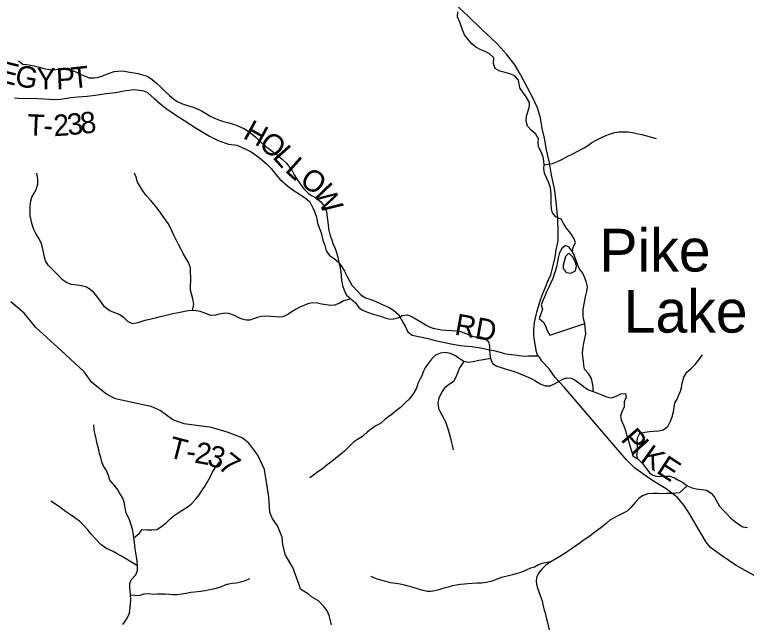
# Model space of a CAD drawing. Extents: x 1578669 to 1989827, y 208020 to 553079.
# Drawn here: x 1756635 to 1766909, y 418953 to 427488 of the extents above; entities that cross this region are included whole.
import ezdxf

# ---------------------------------------------------------------- set-up
doc = ezdxf.new("R2010")
doc.units = 0
for name, color, linetype in [('GM_X_County_Road', 7, 'Continuous'), ('GM_X_County_Road_Text', 7, 'Continuous'), ('GM_X_Major_River', 7, 'Continuous'), ('GM_X_Minor_Lake', 7, 'Continuous'), ('GM_X_Minor_Lake_Text', 7, 'Continuous'), ('GM_X_Minor_River', 7, 'Continuous'), ('GM_X_Township_Road', 7, 'Continuous'), ('GM_X_Township_Road_Text', 7, 'Continuous')]:
    doc.layers.add(name, color=color, linetype=linetype)

msp = doc.modelspace()

# ---------------------------------------------------------------- linework, layer by layer
at = {"layer": 'GM_X_County_Road'}
msp.add_lwpolyline([(1767103, 419565), (1766766, 419751), (1766561, 419891), (1766407, 420005), (1766344, 420080), (1766269, 420203), (1766105, 420488), (1766032, 420597), (1765943, 420706), (1765785, 420826), (1765620, 420928), (1765503, 421004), (1765337, 421122), (1765228, 421233), (1765049, 421440), (1764349, 422257), (1764226, 422391), (1764138, 422512), (1764039, 422622), (1764002, 422675), (1763986, 422694), (1763970, 422721), (1763957, 422767), (1763951, 422809), (1763934, 422909), (1763927, 422984), (1763926, 423058), (1763935, 423164), (1763965, 423308), (1763998, 423420), (1764021, 423498), (1764049, 423572), (1764088, 423659), (1764123, 423743), (1764162, 423835), (1764195, 423963), (1764223, 424083), (1764240, 424185), (1764265, 424311), (1764268, 424449), (1764260, 424620), (1764242, 424810), (1764219, 425017), (1764171, 425238), (1764145, 425407), (1764103, 425587), (1764075, 425752), (1764044, 425887), (1764020, 426037), (1763974, 426178), (1763899, 426337), (1763829, 426468), (1763739, 426648), (1763659, 426783), (1763540, 426931), (1763416, 427074), (1763321, 427164), (1763193, 427279), (1762999, 427472), (1762817, 427640)], dxfattribs=at)
at = {"layer": 'GM_X_Major_River'}
msp.add_lwpolyline([(1764466, 424156), (1764479, 424220), (1764508, 424282), (1764489, 424341), (1764442, 424412), (1764384, 424491), (1764351, 424542), (1764308, 424613), (1764234, 424646), (1764187, 424703), (1764173, 424759), (1764170, 424826), (1764169, 424886), (1764170, 424950), (1764165, 425022), (1764152, 425075), (1764135, 425127), (1764102, 425194), (1764076, 425261), (1764067, 425325), (1764070, 425379), (1764067, 425431), (1764054, 425492), (1764027, 425560), (1763988, 425633), (1763984, 425695), (1763988, 425745), (1763954, 425810), (1763893, 425859), (1763836, 425919), (1763815, 425993), (1763820, 426061), (1763844, 426135), (1763865, 426203), (1763866, 426255), (1763819, 426334), (1763778, 426387), (1763729, 426458), (1763719, 426518), (1763711, 426569), (1763660, 426626), (1763587, 426657), (1763523, 426674), (1763448, 426696), (1763380, 426731), (1763358, 426800), (1763365, 426880), (1763304, 426935), (1763249, 426964), (1763181, 426991), (1763108, 427029), (1763055, 427076), (1763002, 427139), (1762949, 427206), (1762922, 427275), (1762884, 427380), (1762851, 427455), (1762859, 427525)], dxfattribs=at)
at = {"layer": 'GM_X_Minor_Lake'}
for points in [[(1764466, 424156), (1764423, 424223), (1764371, 424246), (1764312, 424199), (1764281, 424126), (1764268, 424074), (1764257, 424020), (1764244, 423948), (1764231, 423896), (1764212, 423842), (1764191, 423784), (1764159, 423711), (1764134, 423659), (1764103, 423593), (1764080, 423536), (1764055, 423480), (1764028, 423410), (1764047, 423350), (1764022, 423284), (1764000, 423222), (1764067, 423165), (1764094, 423102), (1764113, 423052), (1764150, 422985)], [(1764351, 424021), (1764335, 423971), (1764337, 423921), (1764379, 423865), (1764443, 423859), (1764509, 423891), (1764523, 423959), (1764503, 424021), (1764473, 424082), (1764417, 424136), (1764368, 424089)], [(1764639, 423149), (1764624, 423215), (1764617, 423271), (1764617, 423340), (1764628, 423405), (1764639, 423473), (1764652, 423525), (1764671, 423597), (1764679, 423665), (1764660, 423738), (1764643, 423790), (1764614, 423859), (1764561, 423922), (1764536, 423985), (1764517, 424037), (1764496, 424094), (1764466, 424156)], [(1764368, 424089), (1764351, 424021)], [(1764150, 422985), (1764639, 423149)]]:
    msp.add_lwpolyline(points, dxfattribs=at)
at = {"layer": 'GM_X_Minor_River'}
for points in [[(1764466, 424156), (1764479, 424220), (1764508, 424282), (1764489, 424341), (1764442, 424412), (1764384, 424491), (1764351, 424542), (1764308, 424613), (1764234, 424646), (1764187, 424703), (1764173, 424759), (1764170, 424826), (1764169, 424886), (1764170, 424950), (1764165, 425022), (1764152, 425075), (1764135, 425127), (1764102, 425194), (1764076, 425261), (1764067, 425325), (1764070, 425379), (1764067, 425431), (1764054, 425492), (1764027, 425560), (1763988, 425633), (1763984, 425695), (1763988, 425745), (1763954, 425810), (1763893, 425859), (1763836, 425919), (1763815, 425993), (1763820, 426061), (1763844, 426135), (1763865, 426203), (1763866, 426255), (1763819, 426334), (1763778, 426387), (1763729, 426458), (1763719, 426518), (1763711, 426569), (1763660, 426626), (1763587, 426657), (1763523, 426674), (1763448, 426696), (1763380, 426731), (1763358, 426800), (1763365, 426880), (1763304, 426935), (1763249, 426964), (1763181, 426991), (1763108, 427029), (1763055, 427076), (1763002, 427139), (1762949, 427206), (1762922, 427275), (1762884, 427380), (1762851, 427455), (1762859, 427525)], [(1756689, 426841), (1756749, 426793), (1756805, 426785), (1756859, 426779), (1756911, 426769), (1756963, 426753), (1757013, 426739), (1757065, 426728), (1757125, 426718), (1757193, 426714), (1757243, 426720), (1757298, 426722), (1757360, 426718), (1757426, 426710), (1757492, 426684), (1757556, 426652), (1757626, 426622), (1757682, 426602), (1757750, 426600), (1757800, 426606), (1757872, 426630), (1757924, 426650), (1757980, 426672), (1758030, 426688), (1758083, 426696), (1758155, 426698), (1758223, 426686), (1758367, 426662), (1758429, 426644), (1758497, 426622), (1758559, 426582), (1758629, 426519), (1758681, 426473), (1758745, 426413), (1758811, 426351), (1758863, 426303), (1758917, 426266), (1758977, 426240), (1759032, 426220), (1759140, 426188), (1759190, 426170), (1759260, 426136), (1759338, 426088), (1759390, 426056), (1759462, 426022), (1759512, 426005), (1759566, 425987), (1759640, 425969), (1759694, 425955), (1759746, 425937), (1759810, 425909), (1759862, 425883), (1759913, 425849), (1759969, 425809), (1760021, 425769), (1760093, 425696), (1760145, 425650), (1760211, 425600), (1760267, 425558), (1760327, 425516), (1760391, 425459), (1760457, 425397), (1760493, 425347), (1760533, 425293), (1760559, 425240), (1760593, 425184), (1760643, 425110), (1760693, 425040), (1760761, 424977), (1760813, 424945), (1760863, 424913), (1760931, 424861), (1760985, 424795), (1761013, 424723), (1761025, 424640), (1761031, 424578), (1761035, 424528), (1761047, 424456), (1761067, 424381), (1761087, 424327), (1761103, 424273), (1761133, 424205), (1761155, 424148), (1761171, 424080), (1761189, 424008), (1761203, 423946), (1761215, 423871), (1761219, 423817), (1761223, 423757), (1761239, 423685), (1761263, 423616), (1761293, 423550), (1761353, 423498), (1761421, 423440), (1761467, 423375), (1761519, 423337), (1761591, 423307), (1761669, 423281), (1761725, 423265), (1761784, 423247), (1761834, 423229)], [(1764070, 425379), (1764188, 425399), (1764258, 425425), (1764328, 425459), (1764392, 425493), (1764472, 425535), (1764532, 425565), (1764630, 425617), (1764683, 425649), (1764741, 425690), (1764811, 425728), (1764877, 425760), (1764935, 425788), (1764985, 425808), (1765059, 425832), (1765121, 425844), (1765189, 425844), (1765247, 425840), (1765311, 425830), (1765368, 425820), (1765442, 425802), (1765510, 425786), (1765574, 425768), (1765644, 425748)], [(1761353, 423498), (1761251, 423466), (1761199, 423436), (1761125, 423408), (1761075, 423404), (1761007, 423410), (1760941, 423420), (1760888, 423434), (1760810, 423438), (1760752, 423426), (1760640, 423378), (1760588, 423350), (1760532, 423319), (1760470, 423275), (1760402, 423243), (1760352, 423241), (1760296, 423243), (1760232, 423247), (1760155, 423253), (1760099, 423247), (1760043, 423233), (1759989, 423215), (1759937, 423199), (1759885, 423197), (1759831, 423213), (1759775, 423235), (1759723, 423263), (1759643, 423291), (1759589, 423297), (1759507, 423283), (1759457, 423269), (1759386, 423261), (1759320, 423291), (1759240, 423320), (1759184, 423328), (1759134, 423334), (1759078, 423330), (1759018, 423320), (1758960, 423306), (1758906, 423296), (1758854, 423286), (1758798, 423273), (1758724, 423255), (1758661, 423241), (1758609, 423225), (1758533, 423207), (1758463, 423191), (1758365, 423157), (1758291, 423143), (1758223, 423179), (1758173, 423229), (1758095, 423280), (1758027, 423306), (1757963, 423332), (1757895, 423386), (1757855, 423444), (1757801, 423515), (1757746, 423583), (1757696, 423629), (1757642, 423661), (1757580, 423679), (1757518, 423687), (1757430, 423697), (1757362, 423725), (1757308, 423762), (1757238, 423838), (1757176, 423900), (1757104, 423970), (1757070, 424031), (1757052, 424083), (1757038, 424153), (1757026, 424215), (1757012, 424269), (1756980, 424340), (1756934, 424416), (1756906, 424472), (1756882, 424540), (1756868, 424601), (1756854, 424663), (1756852, 424731), (1756854, 424799), (1756862, 424872), (1756878, 424926), (1756910, 424982), (1756938, 425032), (1756962, 425105), (1756960, 425161), (1756954, 425211), (1756944, 425261)], [(1759134, 423334), (1759152, 423422), (1759136, 423494), (1759116, 423567), (1759106, 423617), (1759106, 423687), (1759108, 423743), (1759108, 423797), (1759106, 423872), (1759102, 423934), (1759076, 424006), (1759036, 424076), (1759000, 424135), (1758966, 424197), (1758936, 424259), (1758902, 424327), (1758870, 424392), (1758848, 424442), (1758818, 424502), (1758788, 424552), (1758742, 424620), (1758686, 424701), (1758638, 424769), (1758596, 424819), (1758542, 424883), (1758480, 424946), (1758436, 425014), (1758388, 425086), (1758362, 425136), (1758342, 425207), (1758318, 425261)], [(1761834, 423229), (1761908, 423213), (1761960, 423217), (1762028, 423235), (1762078, 423261), (1762146, 423271), (1762204, 423251), (1762282, 423205), (1762336, 423171), (1762412, 423128), (1762480, 423096), (1762530, 423080), (1762580, 423068), (1762635, 423060), (1762695, 423056), (1762773, 423052), (1762847, 423048), (1762897, 423036), (1762961, 423014), (1763035, 422980), (1763103, 422962), (1763175, 422964), (1763227, 422948), (1763289, 422895), (1763303, 422831), (1763303, 422775), (1763309, 422717), (1763317, 422659), (1763345, 422588), (1763407, 422552), (1763467, 422530), (1763523, 422514), (1763581, 422494), (1763634, 422480), (1763698, 422458), (1763766, 422430), (1763822, 422406), (1763886, 422377), (1763940, 422349), (1764012, 422303), (1764084, 422273), (1764152, 422275), (1764216, 422303), (1764290, 422343), (1764340, 422373), (1764394, 422389), (1764449, 422383), (1764505, 422353), (1764573, 422301), (1764641, 422249), (1764693, 422217), (1764757, 422193), (1764811, 422175), (1764879, 422146), (1764945, 422122), (1765013, 422104), (1765081, 422130), (1765147, 422162), (1765211, 422166), (1765221, 422114), (1765195, 422052), (1765195, 421980), (1765159, 421909), (1765141, 421855), (1765153, 421795), (1765185, 421721), (1765213, 421646), (1765227, 421584), (1765247, 421518), (1765263, 421468), (1765283, 421404), (1765299, 421343), (1765317, 421293), (1765385, 421247), (1765447, 421189), (1765495, 421123), (1765547, 421052), (1765597, 421018), (1765647, 421004), (1765713, 421000), (1765778, 421004), (1765834, 421006), (1765902, 420982), (1765958, 420952), (1766010, 420920), (1766076, 420872), (1766148, 420841), (1766206, 420829), (1766278, 420819), (1766348, 420807), (1766416, 420769), (1766460, 420713), (1766488, 420659), (1766530, 420586), (1766582, 420528), (1766636, 420476), (1766688, 420422), (1766742, 420374), (1766811, 420323), (1766861, 420295), (1766927, 420283)], [(1764757, 422193), (1764757, 422259), (1764747, 422311), (1764735, 422377), (1764691, 422446), (1764637, 422510), (1764629, 422564), (1764621, 422620), (1764611, 422688), (1764609, 422739), (1764617, 422819), (1764627, 422873), (1764653, 423004), (1764639, 423149)], [(1763317, 422659), (1763219, 422640), (1763151, 422632), (1763075, 422612), (1763011, 422604), (1762943, 422614), (1762891, 422647), (1762823, 422695), (1762753, 422729), (1762674, 422741), (1762616, 422731), (1762546, 422703), (1762486, 422651), (1762430, 422576), (1762400, 422526), (1762370, 422470), (1762350, 422416), (1762322, 422362), (1762298, 422305), (1762276, 422241), (1762232, 422161), (1762179, 422091), (1762125, 422040), (1762053, 421968), (1761997, 421928), (1761915, 421862), (1761839, 421806), (1761771, 421747), (1761699, 421707), (1761643, 421665), (1761590, 421627), (1761518, 421565), (1761450, 421523), (1761392, 421482), (1761326, 421420), (1761266, 421358), (1761214, 421314), (1761142, 421254), (1761088, 421214), (1761025, 421163), (1760955, 421109), (1760893, 421067), (1760831, 421021), (1760781, 420983)], [(1765385, 421247), (1765373, 421295), (1765381, 421351), (1765381, 421422), (1765377, 421494), (1765379, 421546), (1765415, 421608), (1765483, 421624), (1765548, 421634), (1765602, 421636), (1765676, 421644), (1765740, 421658), (1765806, 421705), (1765846, 421777), (1765868, 421839), (1765884, 421911), (1765894, 421972), (1765904, 422038), (1765938, 422088), (1765962, 422146), (1765982, 422198), (1765996, 422253), (1766009, 422311), (1766029, 422395), (1766071, 422465), (1766135, 422516), (1766189, 422572), (1766241, 422640), (1766291, 422710)], [(1762943, 422614), (1762881, 422526), (1762853, 422452), (1762826, 422386), (1762796, 422335), (1762724, 422283), (1762668, 422235), (1762630, 422181), (1762590, 422099), (1762576, 422038), (1762588, 421958), (1762616, 421898), (1762660, 421818), (1762684, 421767), (1762704, 421711), (1762726, 421641), (1762746, 421577), (1762760, 421516), (1762780, 421440), (1762790, 421376)], [(1758152, 418923), (1758211, 419004), (1758247, 419082), (1758259, 419162), (1758263, 419212), (1758265, 419273), (1758261, 419339), (1758255, 419389), (1758253, 419443), (1758253, 419500), (1758273, 419550), (1758337, 419620), (1758359, 419682), (1758361, 419748), (1758355, 419813), (1758345, 419871), (1758337, 419927), (1758329, 419987), (1758319, 420074), (1758309, 420142), (1758297, 420210), (1758291, 420260), (1758265, 420335), (1758241, 420405), (1758207, 420477), (1758193, 420533), (1758181, 420588), (1758171, 420642), (1758153, 420698), (1758111, 420764), (1758085, 420816), (1758039, 420877), (1757969, 420951), (1757953, 421015), (1757923, 421084), (1757877, 421154), (1757857, 421206), (1757843, 421270), (1757827, 421324), (1757817, 421375), (1757805, 421429), (1757791, 421481), (1757777, 421535), (1757765, 421587), (1757753, 421654), (1757745, 421728)], [(1758309, 420142), (1758383, 420202), (1758424, 420256), (1758494, 420254), (1758560, 420250), (1758630, 420258), (1758698, 420300), (1758766, 420355), (1758816, 420401), (1758876, 420453), (1758930, 420493), (1758996, 420533), (1759059, 420569), (1759113, 420612), (1759173, 420680), (1759225, 420746), (1759271, 420812), (1759309, 420872), (1759385, 421001), (1759415, 421063), (1759459, 421137), (1759511, 421202)], [(1766076, 420872), (1765970, 420773), (1765918, 420765), (1765862, 420763), (1765789, 420763), (1765721, 420759), (1765667, 420761), (1765595, 420763), (1765525, 420757), (1765449, 420731), (1765397, 420691), (1765351, 420639), (1765285, 420566), (1765233, 420516), (1765178, 420488), (1765122, 420458), (1765052, 420422), (1764992, 420386), (1764942, 420342), (1764882, 420292), (1764814, 420241), (1764762, 420205), (1764710, 420165), (1764644, 420121), (1764594, 420085), (1764539, 420043), (1764485, 420007), (1764435, 419970), (1764379, 419934), (1764311, 419890), (1764241, 419848), (1764165, 419802), (1764099, 419762), (1764035, 419699), (1763995, 419649), (1763966, 419595), (1763956, 419541), (1763960, 419487), (1763974, 419436), (1763996, 419380), (1764014, 419330), (1764040, 419254), (1764050, 419204), (1764066, 419141), (1764084, 419085), (1764100, 419019), (1764114, 418969), (1764138, 418848)], [(1758361, 419748), (1758265, 419803), (1758207, 419841), (1758135, 419881), (1758075, 419917), (1758019, 419947), (1757965, 419971), (1757915, 419995), (1757847, 420046), (1757779, 420116), (1757709, 420190), (1757661, 420252), (1757613, 420309), (1757546, 420373), (1757482, 420423), (1757406, 420473), (1757336, 420520), (1757282, 420560), (1757206, 420612), (1757142, 420654)], [(1764165, 419802), (1764037, 419778), (1763983, 419754), (1763932, 419730), (1763878, 419712), (1763810, 419683), (1763730, 419649), (1763678, 419635), (1763624, 419621), (1763530, 419597), (1763468, 419581), (1763386, 419551), (1763334, 419531), (1763259, 419511), (1763189, 419505), (1763129, 419501), (1763057, 419499), (1762999, 419495), (1762949, 419491), (1762895, 419483), (1762837, 419477), (1762783, 419467), (1762721, 419447), (1762649, 419427), (1762591, 419411), (1762536, 419395), (1762478, 419384), (1762426, 419387), (1762372, 419401), (1762306, 419421), (1762218, 419449), (1762160, 419463), (1762110, 419473), (1762046, 419489), (1761986, 419497), (1761914, 419509), (1761846, 419527), (1761776, 419543), (1761703, 419569), (1761635, 419599)], [(1758261, 419339), (1758385, 419331), (1758451, 419355), (1758513, 419357), (1758583, 419349), (1758635, 419355), (1758689, 419355), (1758748, 419353), (1758802, 419349), (1758852, 419345), (1758916, 419345), (1758976, 419353), (1759044, 419363), (1759110, 419377), (1759162, 419381), (1759242, 419391), (1759310, 419401), (1759396, 419417), (1759450, 419429), (1759531, 419453), (1759591, 419479), (1759643, 419493), (1759693, 419501), (1759747, 419509), (1759811, 419521), (1759875, 419539), (1759937, 419570)]]:
    msp.add_lwpolyline(points, dxfattribs=at)
at = {"layer": 'GM_X_Township_Road'}
for points in [[(1756631, 426321), (1756685, 426316), (1756755, 426312), (1756847, 426315), (1756956, 426311), (1757040, 426304), (1757118, 426299), (1757182, 426297), (1757278, 426302), (1757424, 426322), (1757520, 426333), (1757652, 426344), (1757770, 426356), (1757918, 426381), (1758052, 426395), (1758170, 426416), (1758306, 426434), (1758429, 426421), (1758501, 426394), (1758596, 426309), (1758663, 426248), (1758762, 426169), (1758879, 426091), (1759022, 425995), (1759182, 425895), (1759369, 425779), (1759500, 425717), (1759639, 425668), (1759753, 425654), (1759872, 425605), (1759955, 425560), (1760070, 425481), (1760169, 425391), (1760235, 425326), (1760301, 425241), (1760357, 425177), (1760464, 425085), (1760533, 425032), (1760648, 424955), (1760713, 424916), (1760775, 424863), (1760796, 424823), (1760820, 424773), (1760845, 424722), (1760872, 424642), (1760889, 424559), (1760940, 424424), (1760962, 424322), (1760988, 424246), (1761009, 424171), (1761054, 424104), (1761121, 424062), (1761183, 424013), (1761230, 423944), (1761265, 423886), (1761302, 423809), (1761371, 423690), (1761389, 423670), (1761450, 423603), (1761495, 423552), (1761561, 423511), (1761636, 423489), (1761698, 423462), (1761793, 423419), (1761883, 423380), (1761956, 423335), (1762023, 423274), (1762061, 423211), (1762088, 423159), (1762117, 423112), (1762157, 423034), (1762218, 422985), (1762443, 422940), (1762539, 422913), (1762658, 422888), (1762760, 422863), (1762897, 422843), (1763049, 422825), (1763178, 422806), (1763284, 422783), (1763362, 422770), (1763451, 422747), (1763509, 422730), (1763569, 422721), (1763685, 422706), (1763784, 422693), (1763852, 422694), (1763986, 422694)], [(1761084, 418919), (1761053, 419049), (1761024, 419116), (1760979, 419170), (1760902, 419254), (1760802, 419310), (1760762, 419348), (1760648, 419419), (1760628, 419481), (1760539, 419721), (1760439, 419897), (1760399, 420040), (1760390, 420149), (1760325, 420307), (1760250, 420414), (1760220, 420502), (1760211, 420577), (1760202, 420714), (1760143, 421100), (1760051, 421301), (1759925, 421470), (1759831, 421543), (1759619, 421624), (1759397, 421687), (1759013, 421743), (1758854, 421799), (1758678, 421926), (1758551, 421986), (1758460, 422005), (1758049, 422092), (1757924, 422156), (1757719, 422321), (1757610, 422470), (1757291, 422766), (1756933, 423096), (1756767, 423294), (1756579, 423456)]]:
    msp.add_lwpolyline(points, dxfattribs=at)

# ---------------------------------------------------------------- texts
at = {"layer": 'GM_X_County_Road_Text'}
for s, rotation, p in [('P', 311.177, (1765134, 421516)), ('I', 312.3188, (1765272, 421359)), ('K', 324.5171, (1765406, 421223)), ('E', 326.6465, (1765631, 421063))]:
    msp.add_text(s, height=300, rotation=rotation, dxfattribs=at).set_placement(p)
at = {"layer": 'GM_X_Minor_Lake_Text'}
for s, rotation, p in [('Pike', 359.9987, (1764846, 423880)), ('Lake', 359.999, (1765187, 423022))]:
    msp.add_text(s, height=600, rotation=rotation, dxfattribs=at).set_placement(p)
at = {"layer": 'GM_X_Township_Road_Text'}
for s, rotation, p in [('E', 345.891, (1756387, 426554)), ('G', 349.2495, (1756624, 426495)), ('Y', 359.3505, (1756940, 426440)), ('P', 2.1811, (1757221, 426437)), ('T', 6.1721, (1757446, 426447)), ('T', 357.4406, (1756805, 425792)), ('2', 3.6682, (1757188, 425779)), ('3', 6.0133, (1757386, 425792)), ('8', 6.1497, (1757571, 425811)), ('H', 331.4927, (1759827, 425759)), ('-', 358.3998, (1757035, 425782)), ('O', 321.0722, (1760047, 425641)), ('L', 311.8741, (1760244, 425484)), ('L', 318.0263, (1760418, 425292)), ('O', 325.9493, (1760621, 425114)), ('W', 298.8286, (1760814, 424993)), ('RD', 349.8192, (1762800, 422996)), ('T', 345.5023, (1758776, 421278)), ('2', 349.8934, (1759149, 421198)), ('3', 342.9573, (1759322, 421168)), ('-', 352.1136, (1759030, 421215)), ('7', 321.5458, (1759473, 421127))]:
    msp.add_text(s, height=300, rotation=rotation, dxfattribs=at).set_placement(p)

doc.saveas('drawing.dxf')
